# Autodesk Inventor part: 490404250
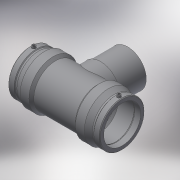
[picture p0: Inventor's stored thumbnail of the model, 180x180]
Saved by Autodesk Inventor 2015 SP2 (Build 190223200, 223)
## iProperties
Created: 2017-06
Part Number: 490404250
Material: Generic
Description: PLASSON TEE 250-250-250
Document SubType Name: Modeling
Designer: KIM
Mass: 17327.5 g
Surface Area: 12195.1 cm^2
Volume: 17327.5 cm^3
Density: 1 g/cm^3
Appearance: Default
Author: KIM
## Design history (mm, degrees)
derived "490404.ipt"
feature "Solid1::490404.ipt"
tag "TaggingFeature1"
body "Solid1"
other parameters: "d0" = 538, "d2" = 326, "d3" = 129, "d4" = 134.5, "d5" = 293.4, "d6" = 237.5, "d8" = 168 deg, "d10" = 51.6, "d11" = 17.2, "d13" = 538, "d14" = 17.6296, "d17" = 225, "d19" = 3.52592, "d20" = 168 deg, "d22" = 303.18, "d23" = 326, "d24" = 294.0846, "d25" = 135 deg, "d26" = 376.6, "d27" = 135 deg, "d29" = 152, "d30" = 15, "d31" = 215.2, "d34" = 5 deg, "d35" = 15, "d39" = 5 deg, "d40" = 9.6, "d41" = 4.8, "d42" = 6, "d43" = 0, "d45" = 4, "d46" = 14, "d47" = 0, "d48" = -315, "d51" = 0, "d54" = 0, "d55" = 293.4, "d56" = 326, "d57" = 188.3, "d58" = 135 deg, "d59" = 129, "d60" = 129, "d61" = 135 deg, "d62" = 315, "d72" = 263.62, "d73" = 131.81, "d74" = -315, "d75" = 262.5, "d77" = 0, "d80" = 0, "d82" = 152, "d83" = 0, "d84" = 3, "d85" = 0, "d86" = 3, "d87" = 0, "d88" = 37.41, "d89" = 9.3525, "d90" = 37.41, "L_" = 538, "L_1" = 129, "D_" = 326, "A_" = 152, "d_2" = 12, "H_" = 315
